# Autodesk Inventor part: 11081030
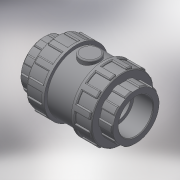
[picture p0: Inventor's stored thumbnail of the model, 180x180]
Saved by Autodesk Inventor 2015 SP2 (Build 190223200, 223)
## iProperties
Created: 2017-11
Part Number: 11081030
Material: Generic
Description: PLASSON CHECK VALVE THR 3" PTFE COATED SPRING + EPDM O-RING
Document SubType Name: Modeling
Designer: KIM
Density: 1 g/cm^3
Appearance: Default
Author: KIM
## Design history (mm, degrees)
derived "110810 - 110610 110910 - 110010.ipt"
feature "Solid1::110810 - 110610 110910 - 110010.ipt"
tag "TaggingFeature1"
body "Solid1"
other parameters: "d1" = 84.926, "d2" = 165, "d3" = 51, "d4" = 67.9408, "d5" = 35.7, "d7" = 118.8964, "d8" = 148.5, "d13" = 2.54778, "d23" = 51, "d24" = 158.4, "d25" = 1.69852, "d26" = 2.54778, "d27" = 24.75, "d28" = 12.375, "d29" = 38.25, "d30" = 0, "d35" = 2.54778, "d39" = 82.5, "d45" = 360 deg, "d47" = 1.69852, "d50" = 82.5, "d51" = 49.5, "d53" = 0, "d54" = 3.3, "d55" = 16.9852, "d56" = 8.4926, "d58" = 0, "d59" = 2.54778, "d61" = 360 deg, "G_" = 84.926, "l_" = 51, "K_" = 165
